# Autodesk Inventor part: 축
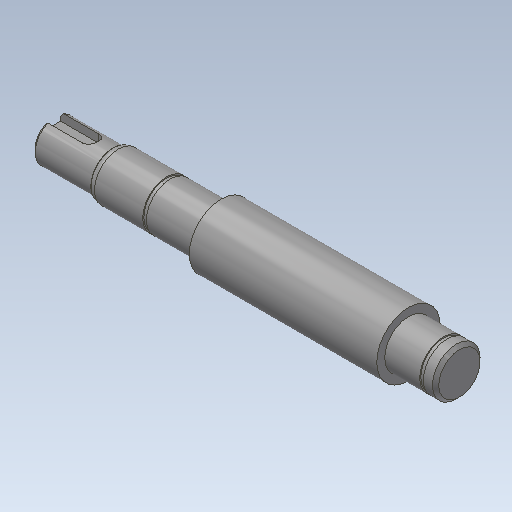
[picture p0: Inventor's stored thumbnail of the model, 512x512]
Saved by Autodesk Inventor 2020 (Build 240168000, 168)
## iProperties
Created: 2015-12
Part Number: 축
Material: 강철, 연강
Document SubType Name: Modeling
Designer: mduedu
Density: 7.86 g/cm^3
Appearance: 강철
Author: mduedu
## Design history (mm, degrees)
sketch "스케치1"
  geometry: L1 (-64, 0)-(64, 0); L2 (-64, 0)-(-64, 6.5); L3 (-64, 6.5)-(-45, 6.5); L4 (-45, 7)-(-44.134, 7.5); L5 (-44.134, 7.5)-(-11, 7.5); L6 (-11, 7.5)-(-11, 10); L7 (-11, 10)-(48, 10); L8 (48, 10)-(48, 7.5); L9 (48, 7.5)-(64, 7.5); L10 (64, 7.5)-(64, 0); L11 (-45, 6.5)-(-45, 7); 2 further points
  constraints: 22 end point, 6 parallel, 2 perpendicular, 1 coincident, 1 horizontal, 1 midpoint, 1 vertical
  dimensions: "d0" = 13 diameter of L3 L1; "d2" = 15 diameter of L5 L1; "d3" = 20 diameter of L7 L1; "d5" = 15 diameter of L9 L1; "d6" = 128 distance of L1.start L1.end; "d7" = 19 distance of L2.end L3.end; "d8" = 34 distance from line of L6 L3.end; "d9" = 59 distance of L6.end L7.end; "d41" = 14 diameter of L4.start L1; "d42" = 30 deg angle of L4 L3
revolve "회전1" sketch "스케치1" stored, may be unused: angle "d11" = 90 deg
node "작업 평면1"
node "작업 평면2"
sketch "스케치3"
  geometry: L1 (9.5, -2.5)-(-2.5, -2.5); L2 (-2.5, 2.5)-(9.5, 2.5); L3 (9.5, 2.5)-(9.5, -2.5); L4 (9.5, 6.5)-(9.5, -6.5) reference; A1 r 2.5 centre (-2.5, 0) between (-2.5, 2.5) and (-2.5, -2.5); 1 further point
  constraints: 6 end point, 2 point on circle, 2 tangent, 1 centre point, 1 collinear, 1 horizontal, 1 horizontal alignment, 1 parallel
  dimensions: "d17" = 5 distance of L2.end L1.start; "d19" = 12 distance from line of A1.centre L3
extrude "돌출2" cut sketch "스케치3" distance "d20" = 3; taper "d21" = 0 deg
chamfer "모따기1" distance "d22" = 1; stored, may be unused: second distance "d23" = 2, angle "d24" = 45 deg
fillet "모깎기1" dims "d25" = 3
sketch "스케치4"
  geometry: L1 (-11, -10)-(-11, 10) reference; L2 (-11, 0)-(0, 0); L3 (-28.15, 12.15)-(-27, 12.15); L4 (-27, 12.15)-(-27, 7.15); L5 (-27, 7.15)-(-28.15, 7.15); L6 (-28.15, 7.15)-(-28.15, 12.15); L7 (59, 12.15)-(60.15, 12.15); L8 (60.15, 12.15)-(60.15, 7.15); L9 (60.15, 7.15)-(59, 7.15); L10 (59, 7.15)-(59, 12.15); L11 (64, -7.5)-(64, 7.5) reference
  constraints: 18 end point, 4 parallel, 2 horizontal, 2 perpendicular, 1 midpoint
  dimensions: "d26" = 16 distance between parallel lines of L4 L1; "d27" = 1.15 distance of L3.start L3.end; "d28" = 14.3 diameter of L5 L2; "d29" = 5 distance of L3.end L4.end; "d30" = 1.15 distance of L7.start L7.end; "d31" = 5 distance of L7.end L8.end; "d32" = 5 distance between parallel lines of L10 L11; "d33" = 14.3 diameter of L9 L2
revolve "회전2" sketch "스케치4" stored, may be unused: angle "d34" = 90 deg
chamfer "모따기2" distance "d35" = 1; stored, may be unused: second distance "d36" = 2, angle "d37" = 45 deg
sketch "스케치5"
  geometry: 2 further points
  constraints: 1 coincident
sketch "스케치6"
  geometry: 1 further point
hole "구멍1" sketch "스케치6" at (2.5, -3.5) diameter "d43" = 4.917; stored, may be unused: countersink angle "d47" = 90 deg, drill point angle "d49" = 120 deg; dims "d44" = 14, "d45" = 4, "d46" = 2, "d48" = 17
node "솔리드1"
other parameters: "d12" = -15.5
